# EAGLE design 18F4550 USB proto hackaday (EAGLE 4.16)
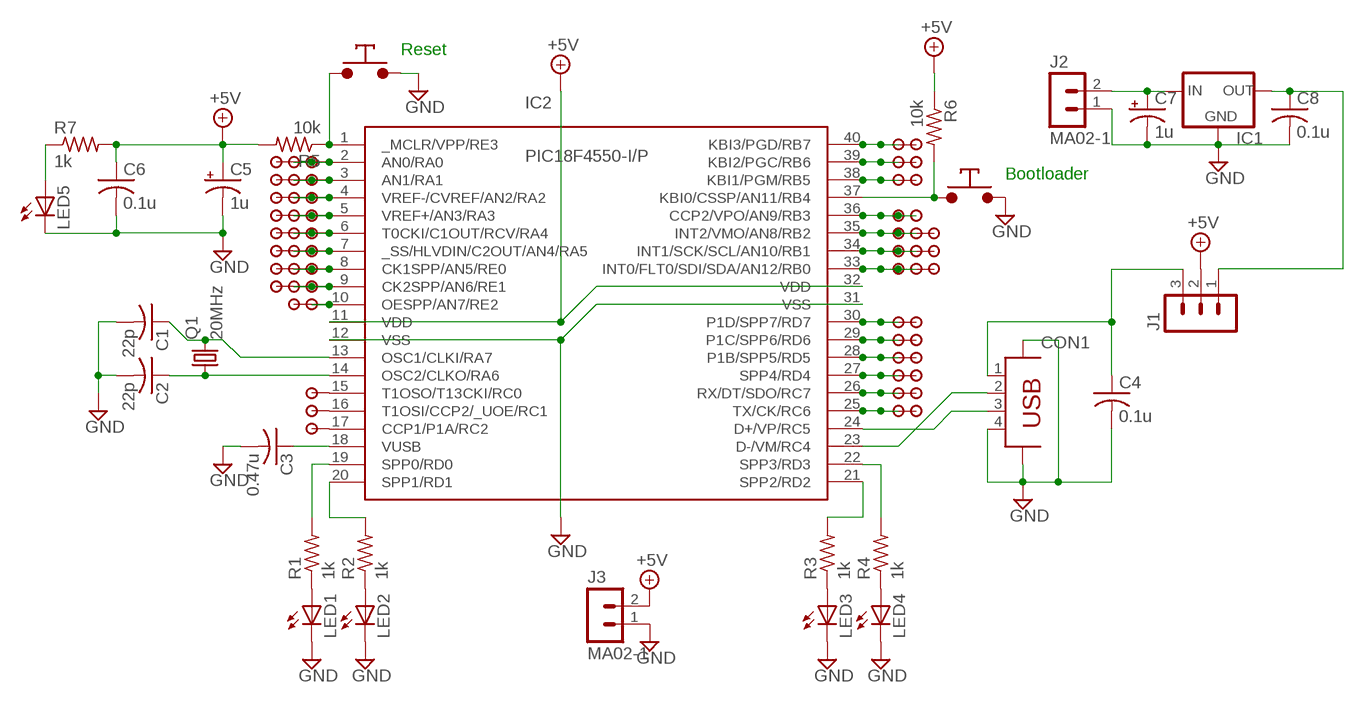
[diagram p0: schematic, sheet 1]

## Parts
C1  22p  C-US050-024X044  [C050-024X044]
C2  22p  C-US050-024X044  [C050-024X044]
C3  0.47u  C-US050-024X044  [C050-024X044]
C4  0.1u  C-USC1206  [C1206]
C5  1u  CPOL-USE2,5-6E  [E2,5-6E]
C6  0.1u  C-USC1206  [C1206]
C7  1u  CPOL-USE2,5-6E  [E2,5-6E]
C8  0.1u  C-USC1206  [C1206]
CON1  PN61729  [PN61729]
IC1  78XXS  [78XXS]
IC2  PIC18F4550-I/P  [DIL40]
J1  MA03-1  [MA03-1]
J2  MA02-1  [MA02-1]
J3  MA02-1  [MA02-1]
LED1  LED3MM  [LED3MM]
LED2  LED3MM  [LED3MM]
LED3  LED3MM  [LED3MM]
LED4  LED3MM  [LED3MM]
LED5  LED3MM  [LED3MM]
Q1  20MHz  CRYTALHC49S  [HC49/S]
R1  1k  R-US_R1206  [R1206]
R2  1k  R-US_R1206  [R1206]
R3  1k  R-US_R1206  [R1206]
R4  1k  R-US_R1206  [R1206]
R5  10k  R-US_R1206  [R1206]
R6  10k  R-US_R1206  [R1206]
R7  1k  R-US_R1206  [R1206]
S1  PUSHBUTTON_NO  [PUSHBUTTON_NO_NARROW]
S2  PUSHBUTTON_NO  [PUSHBUTTON_NO_NARROW]
U$1  DEVPAD  [DEVPAD]
U$2  DEVPAD  [DEVPAD]
U$3  DEVPAD  [DEVPAD]
U$4  DEVPAD  [DEVPAD]
U$6  DEVPAD  [DEVPAD]
U$7  DEVPAD  [DEVPAD]
U$8  DEVPAD  [DEVPAD]
U$9  DEVPAD  [DEVPAD]
U$10  DEVPAD  [DEVPAD]
U$11  DEVPAD  [DEVPAD]
U$12  DEVPAD  [DEVPAD]
U$13  DEVPAD  [DEVPAD]
U$14  DEVPAD  [DEVPAD]
U$15  DEVPAD  [DEVPAD]
U$16  DEVPAD  [DEVPAD]
U$17  DEVPAD  [DEVPAD]
U$18  DEVPAD  [DEVPAD]
U$19  DEVPAD  [DEVPAD]
U$20  DEVPAD  [DEVPAD]
U$21  DEVPAD  [DEVPAD]
U$22  DEVPAD  [DEVPAD]
U$23  DEVPAD  [DEVPAD]
U$24  DEVPAD  [DEVPAD]
U$25  DEVPAD  [DEVPAD]
U$26  DEVPAD  [DEVPAD]
U$27  DEVPAD  [DEVPAD]
U$28  DEVPAD  [DEVPAD]
U$29  DEVPAD  [DEVPAD]
U$30  DEVPAD  [DEVPAD]
U$31  DEVPAD  [DEVPAD]
U$32  DEVPAD  [DEVPAD]
U$33  DEVPAD  [DEVPAD]
U$34  DEVPAD  [DEVPAD]
U$35  DEVPAD  [DEVPAD]
U$36  DEVPAD  [DEVPAD]
U$37  DEVPAD  [DEVPAD]
U$38  DEVPAD  [DEVPAD]
U$39  DEVPAD  [DEVPAD]
U$40  DEVPAD  [DEVPAD]
U$41  DEVPAD  [DEVPAD]
U$42  DEVPAD  [DEVPAD]
U$43  DEVPAD  [DEVPAD]
U$44  DEVPAD  [DEVPAD]
U$45  DEVPAD  [DEVPAD]
U$46  DEVPAD  [DEVPAD]
U$47  DEVPAD  [DEVPAD]
U$48  DEVPAD  [DEVPAD]
U$49  DEVPAD  [DEVPAD]
U$50  DEVPAD  [DEVPAD]
U$51  DEVPAD  [DEVPAD]
U$52  DEVPAD  [DEVPAD]
U$54  DEVPAD  [DEVPAD]
U$55  DEVPAD  [DEVPAD]
U$56  DEVPAD  [DEVPAD]
U$57  DEVPAD  [DEVPAD]
U$58  DEVPAD  [DEVPAD]
U$59  DEVPAD  [DEVPAD]
U$60  DEVPAD  [DEVPAD]

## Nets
+5V: C5.+ C6.1 IC2.11(VDD) IC2.32(VDD) J1.2 J3.2 R5.2 R6.1 R7.2
GND: C1.2 C2.2 C3.2 C4.2 C5.- C6.2 C7.- C8.2 CON1.4 CON1.P$1 CON1.P$2 IC1.GND IC2.12(VSS) IC2.31(VSS) J2.1 J3.1 LED1.K(C) LED2.K(C) LED3.K(C) LED4.K(C) LED5.K(C) S1.P$2 S2.P$2
N$1: C3.1 IC2.18(VUSB)
N$2: CON1.2 IC2.23(D-/VM/RC4)
N$3: CON1.3 IC2.24(D+/VP/RC5)
N$4: LED1.A R1.1
N$5: C2.1 IC2.14(OSC2/CLKO/RA6) Q1.1
N$6: C1.1 IC2.13(OSC1/CLKI/RA7) Q1.2
N$7: IC2.19(SPP0/RD0) R1.2
N$8: IC2.20(SPP1/RD1) R2.2
N$9: IC2.21(SPP2/RD2) R3.2
N$10: IC2.22(SPP3/RD3) R4.2
N$11: LED3.A R3.1
N$12: LED4.A R4.1
N$13: LED2.A R2.1
N$14: IC2.1(_MCLR/VPP/RE3) R5.1 S1.P$1
N$15: IC2.37(KBI0/CSSP/AN11/RB4) R6.2 S2.P$1
N$16: IC2.34(INT1/SCK/SCL/AN10/RB1) U$1.P$1 U$2.P$1 U$3.P$1
N$17: IC2.33(INT0/FLT0/SDI/SDA/AN12/RB0) U$4.P$1 U$6.P$1 U$7.P$1
N$18: IC2.30(P1D/SPP7/RD7) U$19.P$1 U$20.P$1
N$19: IC2.29(P1C/SPP6/RD6) U$21.P$1 U$22.P$1
N$20: IC2.16(T1OSI/CCP2/_UOE/RC1) U$32.P$1
N$21: IC2.17(CCP1/P1A/RC2) U$33.P$1
N$22: IC2.35(INT2/VMO/AN8/RB2) U$8.P$1 U$9.P$1 U$10.P$1
N$23: IC2.36(CCP2/VPO/AN9/RB3) U$11.P$1 U$12.P$1
N$24: IC2.38(KBI1/PGM/RB5) U$13.P$1 U$14.P$1
N$25: IC2.39(KBI2/PGC/RB6) U$15.P$1 U$16.P$1
N$26: IC2.40(KBI3/PGD/RB7) U$17.P$1 U$18.P$1
N$27: IC2.28(P1B/SPP5/RD5) U$23.P$1 U$24.P$1
N$28: IC2.27(SPP4/RD4) U$25.P$1 U$26.P$1
N$29: IC2.26(RX/DT/SDO/RC7) U$27.P$1 U$28.P$1
N$30: IC2.15(T1OSO/T13CKI/RC0) U$34.P$1
N$32: IC2.25(TX/CK/RC6) U$29.P$1 U$30.P$1
N$39: IC2.10(OESPP/AN7/RE2) U$50.P$1 U$51.P$1
N$40: IC2.3(AN1/RA1) U$31.P$1 U$35.P$1 U$52.P$1
N$42: IC2.2(AN0/RA0) U$43.P$1 U$44.P$1 U$54.P$1
N$43: IC2.4(VREF-/CVREF/AN2/RA2) U$36.P$1 U$37.P$1 U$55.P$1
N$44: IC2.5(VREF+/AN3/RA3) U$38.P$1 U$39.P$1 U$56.P$1
N$45: IC2.6(T0CKI/C1OUT/RCV/RA4) U$40.P$1 U$41.P$1 U$57.P$1
N$46: IC2.7(_SS/HLVDIN/C2OUT/AN4/RA5) U$42.P$1 U$45.P$1 U$58.P$1
N$47: IC2.8(CK1SPP/AN5/RE0) U$46.P$1 U$47.P$1 U$59.P$1
N$48: IC2.9(CK2SPP/AN6/RE1) U$48.P$1 U$49.P$1 U$60.P$1
N$65: C4.1 CON1.1 J1.3
N$66: C7.+ IC1.IN J2.2
N$68: C8.1 IC1.OUT J1.1
N$83: LED5.A R7.1

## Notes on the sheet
- Reset
- Bootloader

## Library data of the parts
C1-C4 C6 C8 = rcl:C-US: CAPACITOR, American symbol
C5 C7 = rcl:CPOL-US: POLARIZED CAPACITOR, American symbol
CON1 = con-berg:PN61729: BERG USB connector
IC1 = v-reg:78XXS: VOLTAGE REGULATOR
IC2 = microchip-pic18fxx5x:PIC18*4550: PIC18*4550 Microchip FLASH Microcontroller with FS-USB DEVICE FEATURES FeaturePIC18*4550 Program Memory (bytes) 32k Program Memory (instructions) 16384 I/O Ports Ports A, B, C, D, E Capture/Compare/PWM Modules 1 Enhanced Capture/Compare/PWM Modules 1 Parallel Communications (PSP) Yes 10-bit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
J1 = con-lstb:MA03-1: PIN HEADER
J2 J3 = con-lstb:MA02-1
LED1-LED5 = led:LED: LED
Q1 = crystal:CRYTAL: CRYSTAL
R1-R7 = rcl:R-US_: RESISTOR, American symbol
S1 S2 = misc:PUSHBUTTON_NO
U$1-U$4 U$6-U$52 U$54-U$60 = misc:DEVPAD

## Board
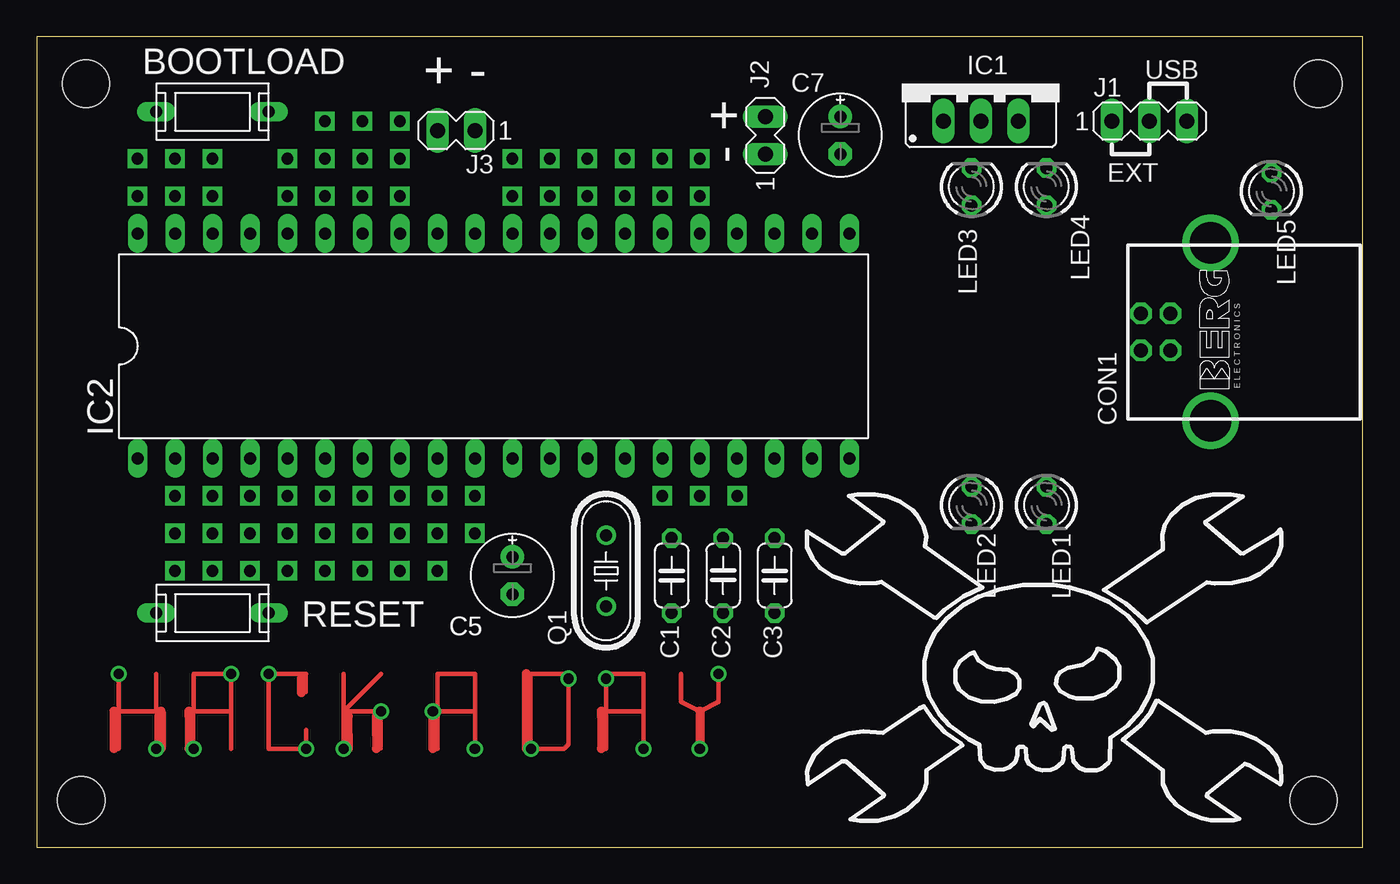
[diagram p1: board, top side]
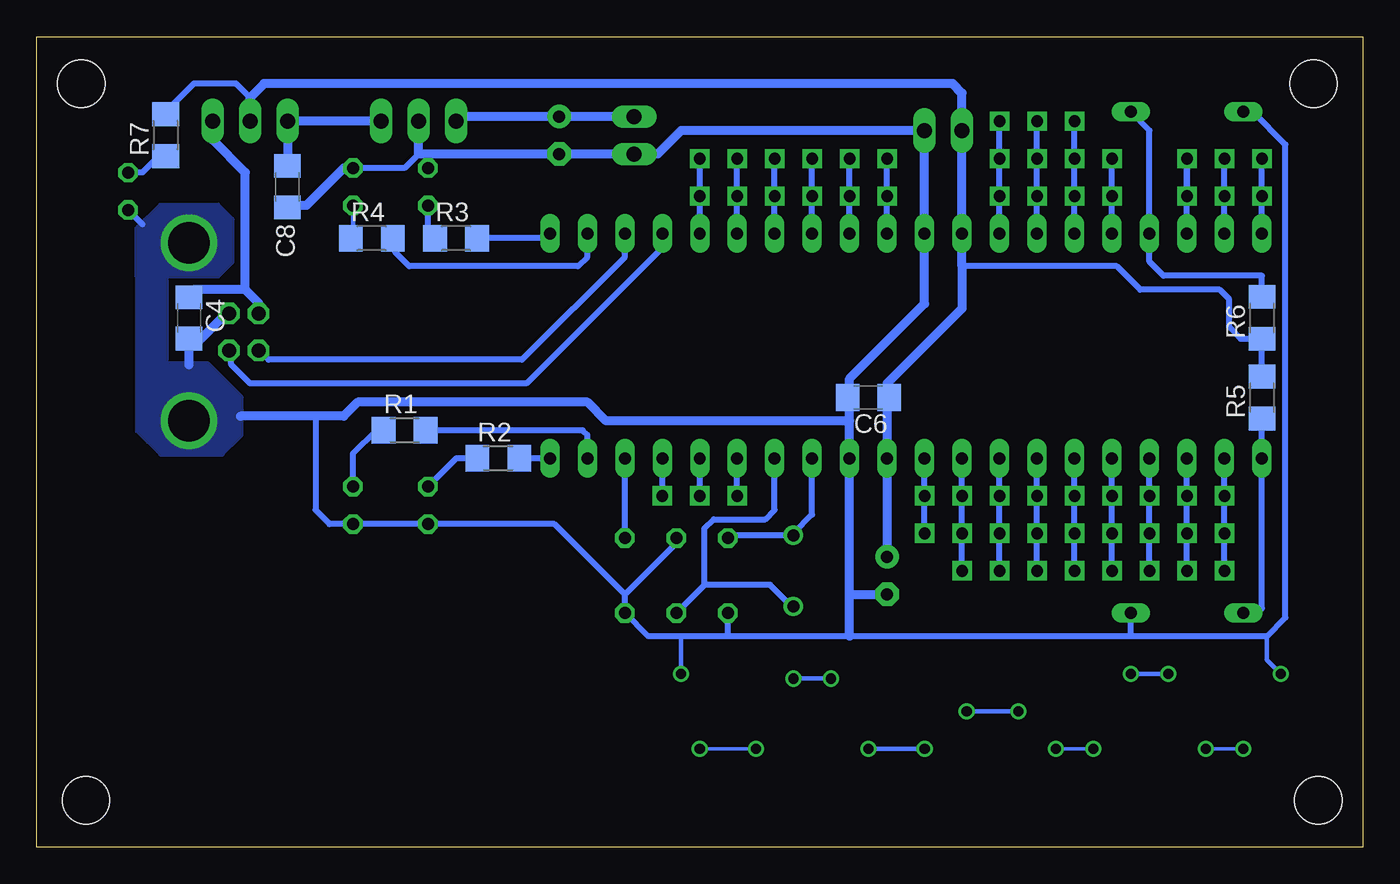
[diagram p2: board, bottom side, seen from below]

Size 89.84 x 54.92 mm. Coordinates in mm from the lower left corner, seen from the top.
Outline: 0,0 89.84,0 89.84,54.92 0,54.92 0,0
Copper layers (1*16): Top 0.035mm / dielectric 1.5mm / Bottom 0.035mm
Design rules "default": minimum track width 10mil, minimum drill 24mil, track to track 8mil, track to pad 8mil, pad to pad 8mil, via to via 8mil, smd to smd 8mil, copper to edge 40mil, drill to drill 8mil, minimum pad ring 10mil, minimum via ring 8mil, stop-mask expansion 4mil, vias tented up to drill 0mil, thermal gap 10mil
Holes 3.2 mm at 3.33,51.75 3.01,3.17 86.51,3.17 86.83,51.75

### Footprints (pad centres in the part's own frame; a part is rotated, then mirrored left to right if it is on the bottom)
C050-024X044 = drill 0.813 octagon: 1 -2.54,0; 2 2.54,0
C1206 = smd 1.6 x 1.8: 1 -1.4,0; 2 1.4,0
E2,5-6E = drill 0.813 pad 1.575 round: + -1.27,0 | drill 0.813 pad 1.575 octagon: - 1.27,0
PN61729 = drill 0.95 octagon: 1 1.25,4.71; 2 -1.25,4.71; 3 -1.25,2.71; 4 1.25,2.71 | drill 2.8 round: P$1 -6.032,0; P$2 6.032,0
78XXS = drill 1.016 long: GND 0,-2.54; IN -2.54,-2.54; OUT 2.54,-2.54
DIL40 = drill 0.813 long: 1 -24.13,-7.62; 2 -21.59,-7.62; 3 -19.05,-7.62; 4 -16.51,-7.62; 5 -13.97,-7.62; 6 -11.43,-7.62; 7 -8.89,-7.62; 8 -6.35,-7.62; 9 -3.81,-7.62; 10 -1.27,-7.62; 11 1.27,-7.62; 12 3.81,-7.62; 13 6.35,-7.62; 14 8.89,-7.62; 15 11.43,-7.62; 16 13.97,-7.62; 17 16.51,-7.62; 18 19.05,-7.62; 19 21.59,-7.62; 20 24.13,-7.62; 21 24.13,7.62; 22 21.59,7.62; 23 19.05,7.62; 24 16.51,7.62; 25 13.97,7.62; 26 11.43,7.62; 27 8.89,7.62; 28 6.35,7.62; 29 3.81,7.62; 30 1.27,7.62; 31 -1.27,7.62; 32 -3.81,7.62; 33 -6.35,7.62; 34 -8.89,7.62; 35 -11.43,7.62; 36 -13.97,7.62; 37 -16.51,7.62; 38 -19.05,7.62; 39 -21.59,7.62; 40 -24.13,7.62
MA03-1 = drill 1.016 long: 1 -2.54,0; 2 0,0; 3 2.54,0
MA02-1 = drill 1.016 long: 1 -2.54,0; 2 0,0
LED3MM = drill 0.813 octagon: A -1.27,0; K 1.27,0
HC49/S = drill 0.813 round: 1 -2.413,0; 2 2.413,0
R1206 = smd 1.6 x 1.803: 1 -1.422,0; 2 1.422,0
PUSHBUTTON_NO_NARROW = drill 0.8 long: P$1 -2.54,0; P$2 5.08,0
DEVPAD = drill 0.8 square: P$1 0,0

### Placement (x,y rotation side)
C1  43.02,18.41 270 top
C2  46.51,18.41 90 top
C3  50,18.41 270 top
C4  79.53,35.87 270 bottom
C5  32.22,18.41 270 top
C6  33.49,30.48 180 bottom
C7  54.45,48.25 270 top
C8  72.86,44.76 270 bottom
CON1  79.53,34.92 90 top
IC1  63.97,51.75 0 top
IC2  30.95,33.97 0 top
J1  75.4,49.21 0 top
J2  49.37,49.52 90 top
J3  27.14,48.57 180 top
LED1  68.41,23.17 270 top
LED2  63.34,23.17 270 top
LED3  63.34,44.76 90 top
LED4  68.41,44.76 90 top
LED5  83.65,44.45 270 top
Q1  38.57,18.73 90 top
R1  64.92,28.25 0 bottom
R2  58.57,26.35 0 bottom
R3  61.43,41.27 0 bottom
R4  67.14,41.27 0 bottom
R5  6.82,30.48 90 bottom
R6  6.82,35.87 90 bottom
R7  81.11,48.25 90 bottom
S1  10.63,15.87 0 top
S2  13.17,49.84 180 top
U$1  22.06,49.21 0 top
U$2  22.06,44.13 0 top
U$3  22.06,46.67 0 top
U$4  24.6,44.13 0 top
U$5  [HACK]  67.78,13.65 0 top
U$6  24.6,46.67 0 top
U$7  24.6,49.21 0 top
U$8  19.52,46.67 0 top
U$9  19.52,49.21 0 top
U$10  19.52,44.13 0 top
U$11  16.98,44.13 0 top
U$12  16.98,46.67 0 top
U$13  11.9,46.67 0 top
U$14  11.9,44.13 0 top
U$15  9.36,46.67 0 top
U$16  9.36,44.13 0 top
U$17  6.82,46.67 0 top
U$18  6.82,44.13 0 top
U$19  32.22,44.13 0 top
U$20  32.22,46.67 0 top
U$21  34.76,44.13 0 top
U$22  34.76,46.67 0 top
U$23  37.3,44.13 0 top
U$24  37.3,46.67 0 top
U$25  39.84,44.13 0 top
U$26  39.84,46.67 0 top
U$27  42.38,44.13 0 top
U$28  42.38,46.67 0 top
U$29  44.92,44.13 0 top
U$30  44.92,46.67 0 top
U$31  11.9,23.81 0 top
U$32  44.92,23.81 0 top
U$33  47.46,23.81 0 top
U$34  42.38,23.81 0 top
U$35  11.9,21.27 0 top
U$36  14.44,23.81 0 top
U$37  14.44,21.27 0 top
U$38  16.98,23.81 0 top
U$39  16.98,21.27 0 top
U$40  19.52,21.27 0 top
U$41  19.52,23.81 0 top
U$42  22.06,21.27 0 top
U$43  9.36,23.81 0 top
U$44  9.36,21.27 0 top
U$45  22.06,23.81 0 top
U$46  24.6,21.27 0 top
U$47  24.6,23.81 0 top
U$48  27.14,23.81 0 top
U$49  27.14,21.27 0 top
U$50  29.68,23.81 0 top
U$51  29.68,21.27 0 top
U$52  11.9,18.73 0 top
U$54  9.36,18.73 0 top
U$55  14.44,18.73 0 top
U$56  16.98,18.73 0 top
U$57  19.52,18.73 0 top
U$58  22.06,18.73 0 top
U$59  24.6,18.73 0 top
U$60  27.14,18.73 0 top

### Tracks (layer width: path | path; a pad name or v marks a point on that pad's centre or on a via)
+5V
  Bottom 0.305: 81.11,49.52 R7.2 81.11,49.84
  Bottom 0.406: 75.4,50.79 76.35,51.75 79.21,51.75 81.11,49.84 | R5.2 R6.1 8.26,34.45 9.04,35.24 9.04,37.14 9.68,37.78 15.08,37.78 16.66,39.36 27.14,39.36 | 32.22,30.48 C6.1
  Bottom 0.61: 75.4,48.89 J1.2 75.4,50.79 74.45,51.75 27.78,51.75 27.14,51.11 J3.2 IC2.32 27.14,39.36 27.14,36.51 32.22,31.43 32.22,30.48 IC2.11 C5.+
GND  (via drill 0.7)
  Top 0.254: v23.33,9.2 23.33,7.62 | 23.33,7.62 23.33,6.66 | 18.25,11.74 18.25,10.47 17.93,10.47 | v10.63,6.66 10.63,8.88 | 10.63,8.88 10.63,9.2 | 8.09,9.2 v8.09,6.66 | 33.49,11.74 v33.49,6.66 | 20.79,7.62 21.11,7.62 | 23.33,7.62 23.01,7.62 | 10.63,8.88 10.31,8.88 | 5.23,8.88 5.55,8.88 | 5.55,9.2 8.41,9.2 | 38.25,8.88 38.57,8.88 38.57,9.2
  Top 0.305: 29.68,9.2 29.68,11.74 27.14,11.74 27.14,9.2 | 29.68,9.2 v29.68,6.66 | 27.14,9.2 29.68,9.2 | 27.14,9.2 27.14,6.66 | 20.79,9.2 20.79,11.74 | 20.79,9.2 v23.33,9.2 | 20.79,9.2 23.33,11.74 | v20.79,6.66 20.79,7.62 20.79,9.2 | 18.25,7.93 v18.25,6.66 15.71,6.66 v15.71,11.74 18.25,11.74 | 13.17,9.2 v13.17,11.74 10.63,11.74 10.63,9.2 13.17,9.2 | 13.17,9.2 13.17,6.66 | 8.09,11.74 8.09,9.2 5.55,9.2 | 5.55,6.66 5.55,8.88 5.55,9.2 | 33.49,11.74 35.71,11.74 v36.03,11.42 36.03,6.98 35.71,6.66 v33.49,6.66 33.17,6.66 | 38.57,9.2 38.57,6.66 | 38.57,9.2 v38.57,11.42 38.57,11.74 41.11,11.74 41.11,9.2 | v41.11,6.66 41.11,9.2 | 41.11,9.2 38.57,9.2 | 43.65,11.74 43.65,9.84 44.92,9.2 46.19,9.84 v46.19,11.74 | 5.55,9.2 v5.55,11.74 | v26.82,9.2 27.14,9.2
  Top 0.61: 44.92,9.2 v44.92,6.66 | 5.23,6.66 5.23,8.88 5.23,9.2 | 8.41,9.2 8.41,6.66 | 10.31,6.66 10.31,8.88 10.31,9.2 | 17.93,10.47 17.93,11.42 | 21.11,6.66 21.11,7.62 21.11,8.88 | 23.01,6.66 23.01,7.62 23.01,8.88 | v26.82,9.2 26.82,6.66 | 33.17,6.66 33.17,11.74 | 38.25,6.66 38.25,8.88 38.25,9.2
  Bottom 0.254: v18.25,6.66 v20.79,6.66 | v8.09,6.66 v10.63,6.66 | v44.92,6.66 v41.11,6.66
  Bottom 0.305: v29.68,6.66 v33.49,6.66 | v13.17,11.74 v15.71,11.74 | v23.33,9.2 v26.82,9.2 | v38.57,11.42 v36.03,11.42 | 6.5,14.28 6.5,12.69 v5.55,11.74 | 46.19,14.28 v46.19,11.74 | 72.86,43.49 C8.2
  Bottom 0.406: 50,17.14 C3.2 48.41,14.28 46.19,14.28 43.02,14.28 | 50,17.14 54.76,21.9 LED2.K LED1.K 70,21.9 70.95,22.86 70.95,29.21 | C2.2 46.51,20.63 50,17.14 | 43.02,14.28 C1.2 | S2.P$2 7.46,49.84 5.23,47.62 5.23,15.55 6.5,14.28 15.71,14.28 | 15.71,14.28 34.76,14.28 43.02,14.28 | 15.71,14.28 S1.P$2 | 63.34,46.98 LED3.K | LED4.K 64.92,46.03 63.97,46.98 | 34.76,30.48 C6.2 | 82.7,42.22 LED5.K
  Bottom 0.61: IC1.GND 63.97,46.98 63.34,46.98 C7.- J2.1 47.78,46.98 46.19,48.57 J3.1 IC2.31 29.68,36.82 34.76,31.75 34.76,30.48 34.76,28.89 | 34.76,28.89 IC2.12 34.76,17.14 | 34.76,17.14 C5.- | 34.76,14.28 34.76,17.14 | LED4.K 69.05,46.03 71.59,43.49 72.86,43.49 | 76.03,29.21 70.95,29.21 69.05,29.21 68.1,30.16 52.54,30.16 51.27,28.89 34.76,28.89 | CON1.4 77.01,36.17 78.89,34.28 79.53,34.28 | 79.53,34.28 C4.2 | 79.53,32.7 79.53,34.28
  pour Bottom (no thermals): 76.03,30.48 78.26,32.7 81.11,32.7 81.11,38.73 83.02,38.73 83.02,28.25 81.43,26.67 77.3,26.67 76.03,27.94
  pour Bottom (no thermals): 83.02,38.73 83.02,41.9 81.43,43.49 77.62,43.49 76.67,42.54 76.67,39.68 77.62,38.73
N$1
  Bottom 0.406: C3.1 IC2.18
N$2
  Bottom 0.406: IC2.23 50,40 56.97,33.03 74.15,33.03 74.78,33.67 CON1.2
N$3
  Bottom 0.406: IC2.24 47.46,40.63 56.67,31.43 75.4,31.43 76.67,32.7 76.67,33.65 76.69,33.67 CON1.3
N$4
  Bottom 0.406: R1.1 66.83,28.25 68.41,26.67 LED1.A
N$5
  Bottom 0.406: Q1.1 38.7,16.32 40.16,17.78 44.6,17.78 | 44.6,17.78 C2.1 | IC2.14 39.84,22.86 40.48,22.22 43.97,22.22 44.6,21.59 44.6,17.78
N$6
  Bottom 0.406: IC2.13 37.3,22.54 38.57,21.27 Q1.2 42.51,21.14 42.7,20.95 C1.1
N$7
  Bottom 0.406: IC2.19 52.54,27.94 52.86,28.25 R1.2
N$8
  Bottom 0.406: IC2.20 R2.2
N$9
  Bottom 0.406: IC2.21 55.08,41.27 R3.2
N$10
  Bottom 0.406: IC2.22 52.54,40 53.18,39.36 64.6,39.36 65.56,40.32 65.56,41.27 R4.2
N$11
  Bottom 0.406: R3.1 63.02,41.27 63.34,41.59 LED3.A
N$12
  Bottom 0.305: R4.1 68.41,41.27 LED4.A
N$13
  Bottom 0.406: R2.1 61.43,26.35 LED2.A
N$14
  Bottom 0.406: R5.1 IC2.1 6.82,16.19 7.14,15.87 S1.P$1
N$15
  Bottom 0.406: R6.2 6.82,38.73 13.49,38.73 14.44,39.68 IC2.37 14.44,48.57 S2.P$1
N$16
  Bottom 0.406: IC2.34 U$2.P$1 U$3.P$1 U$1.P$1
N$17
  Bottom 0.406: IC2.33 U$4.P$1 U$6.P$1 U$7.P$1
N$18
  Bottom 0.406: IC2.30 U$19.P$1 U$20.P$1
N$19
  Bottom 0.406: U$21.P$1 34.76,43.81 | U$21.P$1 U$22.P$1 | IC2.29 U$21.P$1
N$20
  Bottom 0.406: U$32.P$1 IC2.16
N$21
  Bottom 0.406: U$33.P$1 IC2.17
N$22
  Bottom 0.406: U$9.P$1 U$8.P$1 U$10.P$1 IC2.35
N$23
  Bottom 0.406: IC2.36 U$11.P$1 U$12.P$1
N$24
  Bottom 0.406: U$14.P$1 U$13.P$1 IC2.38
N$25
  Bottom 0.406: IC2.39 U$16.P$1 U$15.P$1
N$26
  Bottom 0.406: U$17.P$1 U$18.P$1 IC2.40
N$27
  Bottom 0.406: U$23.P$1 37.3,43.81 | U$23.P$1 U$24.P$1 | IC2.28 U$23.P$1
N$28
  Bottom 0.406: IC2.27 U$25.P$1 U$26.P$1
N$29
  Bottom 0.406: U$28.P$1 U$27.P$1 IC2.26
N$30
  Bottom 0.406: U$34.P$1 IC2.15
N$32
  Bottom 0.406: IC2.25 U$29.P$1 U$30.P$1
N$39
  Bottom 0.406: IC2.10 U$50.P$1 U$51.P$1
N$40
  Bottom 0.406: U$31.P$1 U$35.P$1 U$52.P$1 | U$31.P$1 IC2.3 U$31.P$1
N$42
  Bottom 0.406: IC2.2 U$43.P$1 U$44.P$1 U$54.P$1
N$43
  Bottom 0.406: IC2.4 U$36.P$1 U$37.P$1 U$55.P$1
N$44
  Bottom 0.406: IC2.5 U$38.P$1 U$39.P$1 U$56.P$1
N$45
  Bottom 0.406: IC2.6 U$41.P$1 U$40.P$1 U$57.P$1
N$46
  Bottom 0.406: IC2.7 U$45.P$1 U$42.P$1 U$58.P$1
N$47
  Bottom 0.406: IC2.8 U$47.P$1 U$46.P$1 U$59.P$1
N$48
  Bottom 0.406: IC2.9 U$48.P$1 U$49.P$1 U$60.P$1
N$65
  Bottom 0.61: CON1.1 74.82,36.88 75.72,37.78 | J1.3 77.94,47.94 75.72,45.71 75.72,37.78 | C4.1 79.53,37.46 79.21,37.78 75.72,37.78
N$66
  Bottom 0.61: J2.2 C7.+ 61.11,49.52 IC1.IN
N$68
  Bottom 0.61: IC1.OUT J1.1 C8.1
N$83
  Bottom 0.406: R7.1 81.11,47.3 82.7,45.71 LED5.A

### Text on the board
tNames: BOOTLOAD | USB | + - | - + | EXT | RESET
